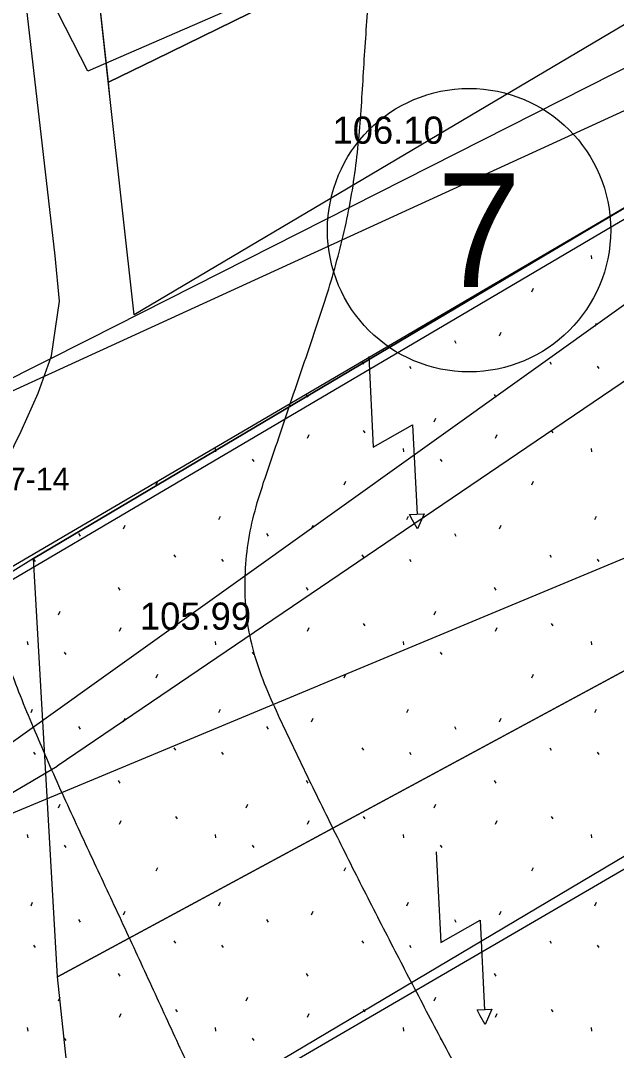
# Model space of a CAD drawing. Extents: x 412225 to 413380, y 4456471 to 4457189.
# Drawn here: x 412987.95 to 413014.24, y 4456785.68 to 4456831.09 of the extents above; entities that cross this region are included whole.
import ezdxf

# ---------------------------------------------------------------- set-up
doc = ezdxf.new("R2010")
doc.units = 0
for name, color, linetype in [('0_HALİHAZIR', 7, 'Continuous'), ('0_KADASTRO', 7, 'Continuous'), ('Level 28', 7, 'Continuous'), ('Level 41', 7, 'Continuous'), ('Level 54', 7, 'Continuous'), ('Level 58', 7, 'Continuous')]:
    doc.layers.add(name, color=color, linetype=linetype)

msp = doc.modelspace()

# ---------------------------------------------------------------- linework, layer by layer
at = {"layer": '0_HALİHAZIR'}
for points in [[(413308.439, 4456995.203), (413040.966, 4456837.39), (412966.32, 4456784.092)], [(413308.103, 4456965.941), (413265.175, 4456940.384), (413047.239, 4456812.664), (412821.475, 4456681.363)], [(412970.39, 4456772.277), (412963.355, 4456768.531), (412962.3, 4456768.36), (412961.145, 4456768.494), (412959.478, 4456769.627), (412958.513, 4456770.745), (412952.047, 4456786.438), (412951.912, 4456787.521), (412952.446, 4456788.778), (412970.248, 4456798.759), (412983.709, 4456807.641), (412986.034, 4456809.786), (412987.013, 4456811.054), (412987.98, 4456812.982), (412988.719, 4456814.662), (412989.314, 4456816.305), (412989.673, 4456818.719), (412989.481, 4456820.71), (412987.098, 4456841.407)], [(413003.312, 4456816.284), (413003.505, 4456812.286), (413005.249, 4456813.266), (413005.444, 4456809.304)], [(413006.296, 4456794.439), (413006.489, 4456790.441), (413008.233, 4456791.42), (413008.428, 4456787.458)]]:
    msp.add_lwpolyline(points, dxfattribs=at)
for points in [[(412997.313, 4456844.81), (413001.922, 4456833.65), (412990.921, 4456828.856), (412988.949, 4456832.725), (412990.073, 4456833.047), (412988.323, 4456837.607), (412989.04, 4456837.767), (412988.613, 4456840.338)], [(413005.108, 4456809.31), (413005.764, 4456809.346), (413005.466, 4456808.673), (413005.25, 4456809.057)], [(413008.092, 4456787.464), (413008.749, 4456787.501), (413008.45, 4456786.828), (413008.234, 4456787.212)]]:
    msp.add_lwpolyline(points, close=True, dxfattribs=at)
for points in [[(413060.346, 4456708.22), (413060.301, 4456708.281), (413058.501, 4456710.672), (413056.576, 4456712.973), (413054.647, 4456715.271), (413052.718, 4456717.568), (413050.787, 4456719.864), (413048.855, 4456722.159), (413046.979, 4456724.498), (413045.159, 4456726.881), (413043.41, 4456729.318), (413041.677, 4456731.766), (413039.953, 4456734.222), (413038.235, 4456736.681), (413036.515, 4456739.139), (413034.789, 4456741.593), (413033.049, 4456744.037), (413031.278, 4456746.458), (413029.471, 4456748.852), (413027.632, 4456751.222), (413025.78, 4456753.582), (413023.933, 4456755.947), (413022.113, 4456758.331), (413020.446, 4456760.815), (413018.97, 4456763.386), (413017.594, 4456766.04), (413016.199, 4456768.694), (413014.728, 4456771.308), (413013.246, 4456773.916), (413011.766, 4456776.526), (413010.304, 4456779.145), (413008.864, 4456781.777), (413007.445, 4456784.421), (413006.042, 4456787.072), (413004.653, 4456789.731), (413003.281, 4456792.399), (413001.932, 4456795.079), (413000.609, 4456797.771), (412999.318, 4456800.479), (412998.238, 4456803.263), (412997.855, 4456806.037), (412998.161, 4456808.93), (412999.038, 4456811.796), (413000, 4456814.638), (413000.967, 4456817.477), (413001.862, 4456820.339), (413002.528, 4456823.251), (413002.905, 4456826.196), (413003.107, 4456829.186), (413003.333, 4456832.174), (413003.673, 4456835.123)], [(413053.765, 4456704.629), (413052.31, 4456706.637), (413050.132, 4456708.695), (413047.877, 4456710.674), (413045.624, 4456712.654), (413043.411, 4456714.678), (413041.28, 4456716.786), (413039.255, 4456718.994), (413037.339, 4456721.3), (413035.515, 4456723.68), (413033.758, 4456726.111), (413032.049, 4456728.576), (413030.368, 4456731.061), (413028.694, 4456733.551), (413027.018, 4456736.039), (413025.261, 4456738.464), (413023.437, 4456740.842), (413021.536, 4456743.163), (413019.636, 4456745.485), (413017.737, 4456747.808), (413015.843, 4456750.134), (413013.957, 4456752.467), (413012.085, 4456754.812), (413010.294, 4456757.215), (413008.638, 4456759.707), (413007.13, 4456762.297), (413005.698, 4456764.933), (413004.283, 4456767.578), (413002.862, 4456770.221), (413001.445, 4456772.865), (413000.033, 4456775.512), (412998.654, 4456778.176), (412997.316, 4456780.86), (412996.027, 4456783.569), (412994.761, 4456786.289), (412993.504, 4456789.013), (412992.244, 4456791.735), (412990.973, 4456794.453), (412989.717, 4456797.177), (412988.513, 4456799.923), (412987.418, 4456802.714), (412986.596, 4456805.581), (412986.333, 4456808.447), (412986.529, 4456810.425)], [(413051.349, 4456693.95), (413048.333, 4456696.344), (413030.862, 4456709.946), (413028.729, 4456712.242), (413018.523, 4456726.182), (413011.437, 4456736.744), (413011.032, 4456737.364), (413003.303, 4456749.579), (412993.015, 4456768.277), (412989.877, 4456774.699), (412989.219, 4456776.109), (412985.414, 4456784.302), (412984.8, 4456785.358), (412980.195, 4456790.588), (412970.682, 4456799.037), (412970.678, 4456799.043)]]:
    msp.add_spline(points, degree=3, dxfattribs=at)
at = {"layer": '0_KADASTRO'}
for points in [[(412990.431, 4456841.028), (412997.401, 4456844.401), (413006.636, 4456849.314), (413015.691, 4456853.599), (413023.936, 4456857.497), (413028.877, 4456847.563), (413029.315, 4456846.694), (413021.206, 4456842.732), (413019.479, 4456841.887), (413012.237, 4456838.349), (413002.16, 4456833.424), (412993.882, 4456829.379), (412991.824, 4456828.374), (412991.475, 4456831.545), (412991.246, 4456833.622)], [(412988.517, 4456807.371), (413039.412, 4456837.541), (413039.961, 4456836.604), (413040.994, 4456834.845), (413043.581, 4456836.363), (413042.548, 4456838.124), (413041.992, 4456839.072), (413062.8, 4456851.406), (413065.741, 4456850.378), (413071.457, 4456840.426), (413074.509, 4456834.757), (412989.577, 4456788.932)], [(412991.824, 4456828.374), (412993.882, 4456829.379), (413002.16, 4456833.424), (413012.237, 4456838.349), (413019.479, 4456841.887), (413021.206, 4456842.732), (413029.315, 4456846.694), (413031.225, 4456842.855), (413032.031, 4456841.233), (412992.963, 4456818.12), (412991.884, 4456827.741)], [(412989.577, 4456788.932), (413081.926, 4456838.759), (413101.802, 4456789.154), (413094.361, 4456785.1), (413093.757, 4456784.771), (413072.6, 4456773.74), (413072.46, 4456773.67), (413051.63, 4456762.814), (413042.762, 4456758.202), (412995.486, 4456733.566)], [(412951.511, 4456794.234), (412953.817, 4456795.602), (412954.075, 4456794.984), (412971.441, 4456805.28), (412982.148, 4456811.63), (412983.585, 4456812.482), (412983.536, 4456812.91), (413038.969, 4456838.295), (413039.412, 4456837.541), (412988.517, 4456807.371), (412984.022, 4456804.579), (412958.009, 4456789.166), (412956.761, 4456788.427), (412954.507, 4456787.092)]]:
    msp.add_lwpolyline(points, close=True, dxfattribs=at)
at = {"layer": 'Level 28'}
msp.add_line((412987.039, 4456806.712), (413035.606, 4456835.154), dxfattribs=at)
msp.add_lwpolyline([(413023.936, 4456857.497), (413028.883, 4456847.552), (413029.315, 4456846.694), (413031.225, 4456842.855), (413032.031, 4456841.233), (412992.963, 4456818.12), (412991.884, 4456827.741), (412990.441, 4456840.933)], dxfattribs=at)
at = {"layer": 'Level 41'}
for p, q in [((413013.125, 4456820.738), (413013.143, 4456820.578)), ((413010.518, 4456819.124), (413010.59, 4456819.284)), ((413009.08, 4456817.186), (413009.151, 4456817.346)), ((413013.29, 4456817.594), (413013.36, 4456817.754)), ((413007.092, 4456816.978), (413007.163, 4456816.872)), ((413003.007, 4456816.049), (413003.078, 4456815.942)), ((413011.3, 4456816.049), (413011.371, 4456815.942)), ((413005.106, 4456815.857), (413005.177, 4456815.75)), ((413013.399, 4456815.857), (413013.47, 4456815.75)), ((413000.551, 4456814.596), (413000.622, 4456814.489)), ((413008.844, 4456814.596), (413008.915, 4456814.489)), ((413006.203, 4456813.403), (413006.274, 4456813.562)), ((413000.609, 4456812.674), (413000.681, 4456812.834)), ((413003.074, 4456813.019), (413003.145, 4456812.912)), ((413008.902, 4456812.674), (413008.974, 4456812.834)), ((413011.367, 4456813.019), (413011.438, 4456812.912)), ((412996.539, 4456812.228), (412996.557, 4456812.068)), ((413004.832, 4456812.228), (413004.85, 4456812.068)), ((413013.125, 4456812.228), (413013.143, 4456812.068)), ((412998.169, 4456811.758), (412998.239, 4456811.651)), ((413006.462, 4456811.758), (413006.532, 4456811.651)), ((412993.932, 4456810.614), (412994.004, 4456810.774)), ((413002.225, 4456810.614), (413002.297, 4456810.774)), ((413010.518, 4456810.614), (413010.59, 4456810.774)), ((412996.704, 4456809.084), (412996.774, 4456809.244)), ((413004.997, 4456809.084), (413005.067, 4456809.244)), ((413013.29, 4456809.084), (413013.36, 4456809.244)), ((412992.494, 4456808.676), (412992.565, 4456808.836)), ((413000.787, 4456808.676), (413000.858, 4456808.836)), ((413009.08, 4456808.676), (413009.151, 4456808.836)), ((412990.506, 4456808.468), (412990.577, 4456808.362)), ((412998.799, 4456808.468), (412998.87, 4456808.362)), ((413007.092, 4456808.468), (413007.163, 4456808.362)), ((412988.52, 4456807.347), (412988.591, 4456807.24)), ((412994.714, 4456807.539), (412994.785, 4456807.432)), ((412996.813, 4456807.347), (412996.884, 4456807.24)), ((413003.007, 4456807.539), (413003.078, 4456807.432)), ((413005.106, 4456807.347), (413005.177, 4456807.24)), ((413011.3, 4456807.539), (413011.371, 4456807.432)), ((413013.399, 4456807.347), (413013.47, 4456807.24)), ((412992.258, 4456806.086), (412992.329, 4456805.979)), ((413000.551, 4456806.086), (413000.622, 4456805.979)), ((413008.844, 4456806.086), (413008.915, 4456805.979)), ((412989.617, 4456804.893), (412989.688, 4456805.052)), ((412997.91, 4456804.893), (412997.981, 4456805.052)), ((413006.203, 4456804.893), (413006.274, 4456805.052)), ((412992.316, 4456804.164), (412992.388, 4456804.324)), ((412994.781, 4456804.509), (412994.852, 4456804.402)), ((413000.609, 4456804.164), (413000.681, 4456804.324)), ((413003.074, 4456804.509), (413003.145, 4456804.402)), ((413008.902, 4456804.164), (413008.974, 4456804.324)), ((413011.367, 4456804.509), (413011.438, 4456804.402)), ((412988.246, 4456803.718), (412988.264, 4456803.558)), ((412996.539, 4456803.718), (412996.557, 4456803.558)), ((413004.832, 4456803.718), (413004.85, 4456803.558)), ((413013.125, 4456803.718), (413013.143, 4456803.558)), ((412989.876, 4456803.248), (412989.946, 4456803.141)), ((412998.169, 4456803.248), (412998.239, 4456803.141)), ((413006.462, 4456803.248), (413006.532, 4456803.141)), ((412993.932, 4456802.104), (412994.004, 4456802.264)), ((413002.225, 4456802.104), (413002.297, 4456802.264)), ((413010.518, 4456802.104), (413010.59, 4456802.264)), ((412988.411, 4456800.574), (412988.481, 4456800.734)), ((412996.704, 4456800.574), (412996.774, 4456800.734)), ((413004.997, 4456800.574), (413005.067, 4456800.734)), ((413013.29, 4456800.574), (413013.36, 4456800.734)), ((412992.494, 4456800.166), (412992.565, 4456800.326)), ((413000.787, 4456800.166), (413000.858, 4456800.326)), ((413009.08, 4456800.166), (413009.151, 4456800.326)), ((412990.506, 4456799.958), (412990.577, 4456799.852)), ((412998.799, 4456799.958), (412998.87, 4456799.852)), ((413007.092, 4456799.958), (413007.163, 4456799.852)), ((412988.52, 4456798.837), (412988.591, 4456798.73)), ((412994.714, 4456799.029), (412994.785, 4456798.922)), ((412996.813, 4456798.837), (412996.884, 4456798.73)), ((413003.007, 4456799.029), (413003.078, 4456798.922)), ((413005.106, 4456798.837), (413005.177, 4456798.73)), ((413011.3, 4456799.029), (413011.371, 4456798.922)), ((413013.399, 4456798.837), (413013.47, 4456798.73)), ((412992.258, 4456797.576), (412992.329, 4456797.469)), ((413000.551, 4456797.576), (413000.622, 4456797.469)), ((413008.844, 4456797.576), (413008.915, 4456797.469)), ((412989.617, 4456796.383), (412989.688, 4456796.542)), ((412997.91, 4456796.383), (412997.981, 4456796.542)), ((413006.203, 4456796.383), (413006.274, 4456796.542)), ((412994.781, 4456795.999), (412994.852, 4456795.892)), ((413003.074, 4456795.999), (413003.145, 4456795.892)), ((413011.367, 4456795.999), (413011.438, 4456795.892)), ((412992.316, 4456795.654), (412992.388, 4456795.814)), ((413000.609, 4456795.654), (413000.681, 4456795.814)), ((413008.902, 4456795.654), (413008.974, 4456795.814)), ((412988.246, 4456795.208), (412988.264, 4456795.048)), ((412996.539, 4456795.208), (412996.557, 4456795.048)), ((413004.832, 4456795.208), (413004.85, 4456795.048)), ((413013.125, 4456795.208), (413013.143, 4456795.048)), ((412989.876, 4456794.738), (412989.946, 4456794.631)), ((412998.169, 4456794.738), (412998.239, 4456794.631)), ((413006.462, 4456794.738), (413006.532, 4456794.631)), ((412993.932, 4456793.594), (412994.004, 4456793.754)), ((413002.225, 4456793.594), (413002.297, 4456793.754)), ((413010.518, 4456793.594), (413010.59, 4456793.754)), ((412988.411, 4456792.064), (412988.481, 4456792.224)), ((412996.704, 4456792.064), (412996.774, 4456792.224)), ((413004.997, 4456792.064), (413005.067, 4456792.224)), ((413013.29, 4456792.064), (413013.36, 4456792.224)), ((412990.506, 4456791.448), (412990.577, 4456791.342)), ((412992.494, 4456791.656), (412992.565, 4456791.816)), ((412998.799, 4456791.448), (412998.87, 4456791.342)), ((413000.787, 4456791.656), (413000.858, 4456791.816)), ((413007.092, 4456791.448), (413007.163, 4456791.342)), ((413009.08, 4456791.656), (413009.151, 4456791.816)), ((412994.714, 4456790.519), (412994.785, 4456790.412)), ((413003.007, 4456790.519), (413003.078, 4456790.412)), ((413011.3, 4456790.519), (413011.371, 4456790.412)), ((412988.52, 4456790.327), (412988.591, 4456790.22)), ((412996.813, 4456790.327), (412996.884, 4456790.22)), ((413005.106, 4456790.327), (413005.177, 4456790.22)), ((413013.399, 4456790.327), (413013.47, 4456790.22)), ((412992.258, 4456789.066), (412992.329, 4456788.959)), ((413000.551, 4456789.066), (413000.622, 4456788.959)), ((413008.844, 4456789.066), (413008.915, 4456788.959)), ((412989.617, 4456787.873), (412989.688, 4456788.032)), ((412997.91, 4456787.873), (412997.981, 4456788.032)), ((413006.203, 4456787.873), (413006.274, 4456788.032)), ((412994.781, 4456787.489), (412994.852, 4456787.382)), ((413003.074, 4456787.489), (413003.145, 4456787.382)), ((413011.367, 4456787.489), (413011.438, 4456787.382)), ((412992.316, 4456787.144), (412992.388, 4456787.304)), ((413000.609, 4456787.144), (413000.681, 4456787.304)), ((413008.902, 4456787.144), (413008.974, 4456787.304)), ((412988.246, 4456786.698), (412988.264, 4456786.538)), ((412996.539, 4456786.698), (412996.557, 4456786.538)), ((413004.832, 4456786.698), (413004.85, 4456786.538)), ((413013.125, 4456786.698), (413013.143, 4456786.538)), ((412989.876, 4456786.228), (412989.946, 4456786.121)), ((412998.169, 4456786.228), (412998.239, 4456786.121)), ((413006.462, 4456786.228), (413006.532, 4456786.121))]:
    msp.add_line(p, q, dxfattribs=at)
at = {"layer": 'Level 54'}
for p, q in [((413042.649, 4456834.214), (412989.559, 4456798.214)), ((413020.471, 4456831.952), (412990.953, 4456817.034)), ((413042.792, 4456819.117), (412970.517, 4456789.026)), ((412990.953, 4456817.034), (412981.365, 4456812.189))]:
    msp.add_line(p, q, dxfattribs=at)
for points in [[(412772.861, 4456680.089), (413040.614, 4456837.658)], [(412772.521, 4456650.705), (412780.988, 4456655.646), (413046.364, 4456813.097)], [(412936.582, 4456767.038), (412989.559, 4456798.214)]]:
    msp.add_lwpolyline(points, dxfattribs=at)
at = {"layer": 'Level 58'}
msp.add_circle((413007.742, 4456821.848), 6.25, dxfattribs=at)

# ---------------------------------------------------------------- texts
at = {"layer": '0_HALİHAZIR'}
for s, p in [('106.10 ', (413001.714, 4456825.657)), ('105.99 ', (412993.214, 4456804.23))]:
    msp.add_text(s, height=1.2, dxfattribs=at).set_placement(p)
at = {"layer": '0_KADASTRO'}
msp.add_text('01-6157-14', height=1, dxfattribs=at).set_placement((412983.267, 4456810.372))
msp.add_text('01-6157-14', height=1, dxfattribs=at).set_placement((412983.267, 4456810.372))
at = {"layer": 'Level 58'}
msp.add_text('7', height=5, dxfattribs=at).set_placement((413006.324, 4456819.348))

doc.saveas('drawing.dxf')
